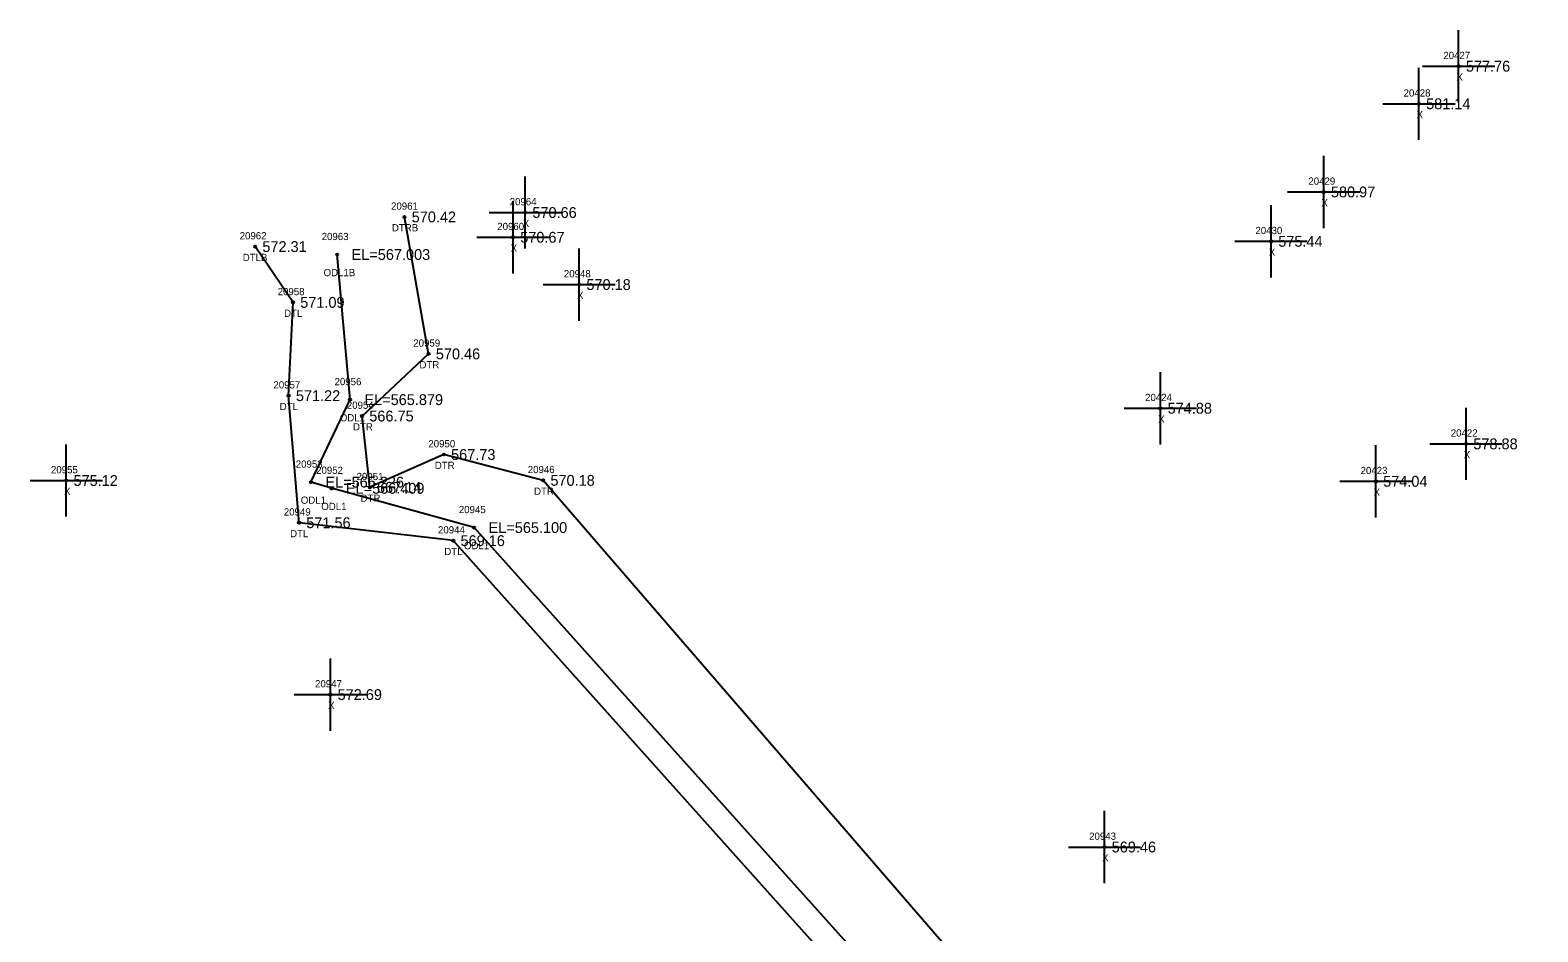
# Model space of a CAD drawing. Extents: x 1695443 to 1696344, y 1087542 to 1090645.
# Drawn here: x 1695443.4 to 1695652.1, y 1089240.5 to 1089365.4 of the extents above; entities that cross this region are included whole.
import ezdxf

# ---------------------------------------------------------------- set-up
doc = ezdxf.new("R2010")
doc.units = 0
for name, color, linetype in [('RD_EX_H2O', 7, 'Continuous'), ('RD_EX_H2O_txCode', 7, 'Continuous'), ('RD_EX_Misc', 7, 'Continuous'), ('RD_EX_Misc_txCode', 7, 'Continuous'), ('RD_EX_TX_H2O_ELEV', 7, 'Continuous'), ('RD_EX_TX_Misc_ELEV', 7, 'Continuous'), ('RD_SMD_Locator', 7, 'Continuous')]:
    doc.layers.add(name, color=color, linetype=linetype)

msp = doc.modelspace()

# ---------------------------------------------------------------- linework, layer by layer
at = {"layer": 'RD_EX_H2O'}
for points in [[(1695741.44, 1088979.77), (1695735.36, 1088982.13), (1695733.74, 1089010.53), (1695714.12, 1089041.46), (1695688.87, 1089060.37), (1695655.87, 1089102.57), (1695608.91, 1089121.01), (1695600.2, 1089162.09), (1695581.57, 1089225.22), (1695514.41, 1089303.03), (1695500.66, 1089306.61), (1695490.41, 1089302.07), (1695489.34, 1089311.94), (1695498.55, 1089320.55), (1695495.21, 1089339.52)], [(1695727.71, 1088968.15), (1695711.81, 1088974.31), (1695709.85, 1089000.95), (1695713.57, 1089012.1), (1695692.24, 1089031.37), (1695674.55, 1089053.33), (1695643.83, 1089091.02), (1695600.78, 1089108.48), (1695586.08, 1089153.06), (1695562.04, 1089227.51), (1695501.97, 1089294.68), (1695480.62, 1089297.16), (1695479.18, 1089314.76), (1695479.78, 1089327.68), (1695474.54, 1089335.41)], [(1695742.91, 1088967.28), (1695718.08, 1088980.23), (1695718.13, 1089011.92), (1695699.88, 1089034.17), (1695684.21, 1089056.74), (1695648.51, 1089095.47), (1695602.44, 1089110.75), (1695589.22, 1089153.92), (1695564.5, 1089229.98), (1695504.85, 1089296.49), (1695485.1, 1089301.93), (1695482.27, 1089302.79), (1695487.67, 1089314.21), (1695485.89, 1089334.31)]]:
    msp.add_lwpolyline(points, dxfattribs=at)
at = {"layer": 'RD_EX_Misc'}
for p, q in [((1695641.11, 1089355.39), (1695641.11, 1089365.39)), ((1695635.61, 1089350.19), (1695635.61, 1089360.19)), ((1695636.11, 1089360.39), (1695646.11, 1089360.39)), ((1695630.61, 1089355.19), (1695640.61, 1089355.19)), ((1695622.43, 1089337.98), (1695622.43, 1089347.98)), ((1695511.91, 1089335.13), (1695511.91, 1089345.13)), ((1695510.23, 1089331.7), (1695510.23, 1089341.7)), ((1695615.14, 1089331.14), (1695615.14, 1089341.14)), ((1695617.43, 1089342.98), (1695627.43, 1089342.98)), ((1695506.91, 1089340.13), (1695516.91, 1089340.13)), ((1695505.23, 1089336.7), (1695515.23, 1089336.7)), ((1695519.39, 1089325.15), (1695519.39, 1089335.15)), ((1695610.14, 1089336.14), (1695620.14, 1089336.14)), ((1695514.39, 1089330.15), (1695524.39, 1089330.15)), ((1695599.83, 1089308.02), (1695599.83, 1089318.02)), ((1695594.83, 1089313.02), (1695604.83, 1089313.02)), ((1695642.14, 1089303.09), (1695642.14, 1089313.09)), ((1695448.4, 1089298.01), (1695448.4, 1089308.01)), ((1695629.66, 1089297.9), (1695629.66, 1089307.9)), ((1695637.14, 1089308.09), (1695647.14, 1089308.09)), ((1695443.4, 1089303.01), (1695453.4, 1089303.01)), ((1695624.66, 1089302.9), (1695634.66, 1089302.9)), ((1695484.95, 1089268.36), (1695484.95, 1089278.36)), ((1695479.95, 1089273.36), (1695489.95, 1089273.36)), ((1695592.09, 1089247.25), (1695592.09, 1089257.25)), ((1695587.09, 1089252.25), (1695597.09, 1089252.25))]:
    msp.add_line(p, q, dxfattribs=at)
at = {"layer": 'RD_SMD_Locator'}
for centre in [(1695641.11, 1089360.39), (1695635.61, 1089355.19), (1695622.43, 1089342.98), (1695495.21, 1089339.52), (1695511.91, 1089340.13), (1695474.54, 1089335.41), (1695510.23, 1089336.7), (1695615.14, 1089336.14), (1695485.89, 1089334.31), (1695519.39, 1089330.15), (1695479.78, 1089327.68), (1695498.55, 1089320.55), (1695479.18, 1089314.76), (1695487.67, 1089314.21), (1695489.34, 1089311.94), (1695599.83, 1089313.02), (1695642.14, 1089308.09), (1695500.66, 1089306.61), (1695448.4, 1089303.01), (1695482.27, 1089302.79), (1695485.1, 1089301.93), (1695490.41, 1089302.07), (1695514.41, 1089303.03), (1695629.66, 1089302.9), (1695480.62, 1089297.16), (1695504.85, 1089296.49), (1695501.97, 1089294.68), (1695484.95, 1089273.36), (1695592.09, 1089252.25)]:
    msp.add_circle(centre, 0.15, dxfattribs=at)

# ---------------------------------------------------------------- texts
at = {"layer": 'RD_EX_H2O_txCode'}
for s, p in [('20961', (1695493.35, 1089340.52)), ('20962', (1695472.4, 1089336.41)), ('20963', (1695483.75, 1089336.31)), ('DTRB', (1695493.47, 1089337.52)), ('DTLB', (1695472.82, 1089333.41)), ('ODL1B', (1695484.01, 1089331.31)), ('20958', (1695477.66, 1089328.68)), ('DTL', (1695478.54, 1089325.68)), ('20959', (1695496.43, 1089321.55)), ('DTR', (1695497.28, 1089318.55)), ('20957', (1695477.07, 1089315.76)), ('20956', (1695485.53, 1089316.21)), ('DTL', (1695477.94, 1089312.76)), ('ODL1', (1695486.26, 1089311.21)), ('20954', (1695487.23, 1089312.94)), ('DTR', (1695488.08, 1089309.94)), ('20950', (1695498.51, 1089307.61)), ('20953', (1695480.16, 1089304.79)), ('20952', (1695482.98, 1089303.93)), ('20951', (1695488.58, 1089303.07)), ('DTR', (1695499.4, 1089304.61)), ('20946', (1695512.27, 1089304.03)), ('DTR', (1695513.14, 1089301.03)), ('ODL1', (1695480.86, 1089299.79)), ('ODL1', (1695483.69, 1089298.93)), ('DTR', (1695489.14, 1089300.07)), ('20945', (1695502.73, 1089298.49)), ('20949', (1695478.51, 1089298.16)), ('DTL', (1695479.38, 1089295.16)), ('20944', (1695499.85, 1089295.68)), ('DTL', (1695500.72, 1089292.68)), ('ODL1', (1695503.44, 1089293.49))]:
    msp.add_text(s, height=1, dxfattribs=at).set_placement(p)
at = {"layer": 'RD_EX_Misc_txCode'}
for s, p in [('20427', (1695638.99, 1089361.39)), ('X', (1695640.8, 1089358.39)), ('20428', (1695633.49, 1089356.19)), ('X', (1695635.29, 1089353.19)), ('20429', (1695620.31, 1089343.98)), ('20964', (1695509.77, 1089341.13)), ('X', (1695622.12, 1089340.98)), ('X', (1695511.59, 1089338.13)), ('20960', (1695508.05, 1089337.7)), ('20430', (1695612.98, 1089337.14)), ('X', (1695509.91, 1089334.7)), ('X', (1695614.83, 1089334.14)), ('20948', (1695517.27, 1089331.15)), ('X', (1695519.08, 1089328.15)), ('20424', (1695597.71, 1089314.02)), ('X', (1695599.52, 1089311.02)), ('20422', (1695640.02, 1089309.09)), ('X', (1695641.82, 1089306.09)), ('20955', (1695446.28, 1089304.01)), ('20423', (1695627.54, 1089303.9)), ('X', (1695448.09, 1089301.01)), ('X', (1695629.34, 1089300.9)), ('20947', (1695482.83, 1089274.36)), ('X', (1695484.64, 1089271.36)), ('20943', (1695589.97, 1089253.25)), ('X', (1695591.77, 1089250.25))]:
    msp.add_text(s, height=1, dxfattribs=at).set_placement(p)
at = {"layer": 'RD_EX_TX_H2O_ELEV'}
for s, p in [('570.42', (1695496.21, 1089338.77)), ('572.31', (1695475.54, 1089334.66)), ('EL=567.003', (1695487.89, 1089333.56)), ('571.09', (1695480.78, 1089326.93)), ('570.46', (1695499.55, 1089319.8)), ('571.22', (1695480.18, 1089314.01)), ('EL=565.879', (1695489.67, 1089313.46)), ('566.75', (1695490.34, 1089311.19)), ('567.73', (1695501.66, 1089305.86)), ('570.18', (1695515.41, 1089302.28)), ('EL=565.226', (1695484.27, 1089302.04)), ('EL=566.409', (1695487.1, 1089301.18)), ('567.14', (1695491.41, 1089301.32)), ('571.56', (1695481.62, 1089296.41)), ('569.16', (1695502.97, 1089293.93)), ('EL=565.100', (1695506.85, 1089295.74))]:
    msp.add_text(s, height=1.5, dxfattribs=at).set_placement(p)
at = {"layer": 'RD_EX_TX_Misc_ELEV'}
for s, p in [('577.76', (1695642.11, 1089359.64)), ('581.14', (1695636.61, 1089354.44)), ('580.97', (1695623.43, 1089342.23)), ('570.66', (1695512.91, 1089339.38)), ('570.67', (1695511.23, 1089335.95)), ('575.44', (1695616.14, 1089335.39)), ('570.18', (1695520.39, 1089329.4)), ('574.88', (1695600.83, 1089312.27)), ('578.88', (1695643.14, 1089307.34)), ('575.12', (1695449.4, 1089302.26)), ('574.04', (1695630.66, 1089302.15)), ('572.69', (1695485.95, 1089272.61)), ('569.46', (1695593.09, 1089251.5))]:
    msp.add_text(s, height=1.5, dxfattribs=at).set_placement(p)

doc.saveas('drawing.dxf')
